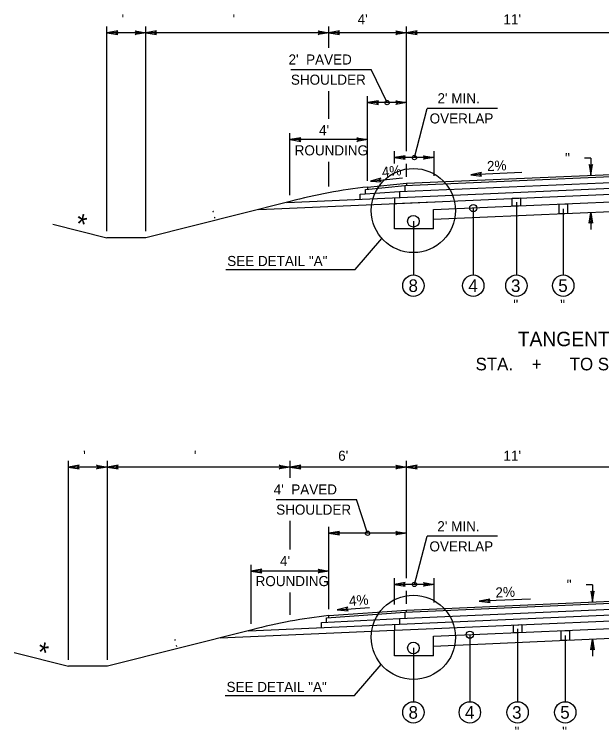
# Model space of a CAD drawing. Extents: x -592 to 1199, y -590 to 416.
# Drawn here: x -127.8 to -46.2, y 170.1 to 269.4 of the extents above; entities that cross this region are included whole.
import ezdxf

# ---------------------------------------------------------------- set-up
doc = ezdxf.new("R2010")
doc.units = 0
doc.layers.add('1', color=7, linetype='Continuous')
doc.layers.add('Des_ Drain_ Ftrs', color=7, linetype='Continuous')

msp = doc.modelspace()

# ---------------------------------------------------------------- linework, layer by layer
at = {"layer": '1'}
for p, q in [((-114.945, 239.248), (-114.945, 267.693)), ((-109.556, 239.248), (-109.556, 267.693)), ((-84.139, 264.7), (-84.139, 267.693)), ((-73.363, 250.367), (-73.363, 267.693)), ((-109.556, 266.813), (-114.945, 266.813)), ((-84.139, 266.813), (-109.556, 266.813)), ((-73.363, 266.813), (-84.139, 266.813)), ((-43.728, 266.813), (-73.363, 266.813)), ((-89.405, 261.692), (-78.264, 261.692)), ((-76.057, 257.11), (-78.264, 261.692)), ((-84.145, 254.87), (-84.145, 258.709)), ((-78.751, 246.264), (-78.751, 257.99)), ((-73.363, 257.11), (-78.751, 257.11)), ((-72.262, 249.487), (-70.472, 256.314)), ((-60.708, 256.314), (-70.472, 256.314)), ((-89.533, 244.254), (-89.533, 252.851)), ((-78.751, 251.971), (-89.528, 251.971)), ((-75.005, 248.668), (-75.005, 250.367)), ((-69.519, 246.958), (-69.519, 250.367)), ((-69.519, 249.487), (-75.005, 249.487)), ((-47.754, 249.397), (-48.634, 249.397)), ((-47.754, 249.397), (-47.754, 247.028)), ((-84.145, 245.487), (-84.145, 248.897)), ((-73.363, 246.79), (-73.363, 248.607)), ((-73.369, 245.91), (-43.728, 247.204)), ((-57.336, 247.389), (-64.422, 247.08)), ((-78.37, 246.214), (-73.893, 246.651)), ((-73.603, 245.601), (-43.728, 246.906)), ((-89.953, 243.269), (-43.728, 245.287)), ((-79.055, 245.054), (-73.603, 245.601)), ((-78.751, 245.384), (-73.369, 245.91)), ((-78.751, 245.384), (-78.751, 245.084)), ((-74.306, 244.762), (-43.728, 246.097)), ((-73.603, 245.601), (-73.603, 244.792)), ((-73.368, 245.91), (-73.368, 245.61)), ((-93.874, 242.289), (-43.728, 244.478)), ((-79.783, 244.397), (-74.306, 244.762)), ((-79.783, 243.713), (-79.783, 244.397)), ((-79.055, 244.446), (-79.055, 245.054)), ((-74.306, 244.762), (-74.306, 243.952)), ((-89.528, 243.376), (-109.556, 238.368)), ((-75.01, 243.922), (-75.01, 242.964)), ((-75.01, 243.113), (-69.524, 243.352)), ((-69.621, 242.269), (-43.728, 243.4)), ((-58.086, 243.311), (-58.086, 233.194)), ((-75.01, 239.574), (-75.01, 243.113)), ((-69.621, 239.574), (-69.621, 242.269)), ((-64.079, 242.482), (-64.079, 233.194)), ((-51.585, 242.384), (-51.585, 233.194)), ((-69.621, 240.921), (-43.728, 242.052)), ((-47.754, 241.876), (-47.754, 239.508)), ((-122.48, 240.251), (-114.945, 238.368)), ((-72.396, 240.645), (-72.396, 233.194)), ((-69.621, 239.574), (-75.01, 239.574)), ((-109.556, 238.368), (-114.945, 238.368)), ((-80.5, 233.931), (-76.76, 238.25)), ((-98.431, 233.931), (-80.5, 233.931)), ((-120.277, 179.796), (-120.277, 207.406)), ((-114.888, 206.526), (-120.277, 206.526)), ((-114.888, 179.796), (-114.888, 207.406)), ((-89.528, 206.526), (-114.888, 206.526)), ((-89.528, 205.027), (-89.528, 207.406)), ((-73.363, 206.526), (-89.528, 206.526)), ((-73.363, 191.138), (-73.363, 207.406)), ((-43.728, 206.526), (-73.363, 206.526)), ((-91.442, 202.027), (-80.301, 202.027)), ((-78.751, 197.356), (-80.301, 202.027)), ((-89.528, 195.085), (-89.528, 199.058)), ((-84.14, 186.794), (-84.14, 198.236)), ((-73.363, 197.356), (-84.14, 197.356)), ((-72.262, 190.258), (-70.5, 196.924)), ((-60.736, 196.924), (-70.5, 196.924)), ((-94.916, 184.788), (-94.916, 192.989)), ((-84.14, 192.109), (-94.916, 192.109)), ((-75.005, 187.452), (-75.005, 191.138)), ((-69.519, 187.738), (-69.519, 191.138)), ((-69.519, 190.258), (-75.005, 190.258)), ((-47.527, 190.188), (-48.407, 190.188)), ((-47.527, 190.188), (-47.527, 187.819)), ((-89.528, 186.017), (-89.528, 189.128)), ((-73.363, 187.57), (-73.363, 189.378)), ((-73.603, 186.381), (-43.728, 187.685)), ((-73.372, 186.69), (-43.728, 187.985)), ((-56.156, 188.213), (-63.242, 187.903)), ((-84.138, 185.914), (-73.372, 186.69)), ((-82.965, 186.742), (-78.478, 187.065)), ((-74.31, 185.541), (-43.728, 186.876)), ((-73.372, 186.389), (-73.372, 186.69)), ((-95.284, 183.816), (-43.728, 186.067)), ((-84.442, 185.592), (-73.603, 186.381)), ((-84.138, 185.614), (-84.138, 185.914)), ((-73.603, 186.381), (-73.603, 185.566)), ((-85.17, 184.942), (-74.31, 185.541)), ((-85.17, 184.257), (-85.17, 184.942)), ((-84.442, 184.982), (-84.442, 185.592)), ((-75.01, 184.699), (-75.01, 183.892)), ((-74.31, 185.541), (-74.31, 184.726)), ((-69.524, 184.131), (-43.728, 185.258)), ((-94.788, 183.94), (-114.888, 178.916)), ((-99.206, 182.835), (-75.01, 183.892)), ((-75.01, 183.892), (-69.524, 184.132)), ((-75.01, 180.354), (-75.01, 183.892)), ((-69.621, 183.048), (-43.728, 184.179)), ((-57.926, 184.098), (-57.926, 173.973)), ((-69.621, 180.354), (-69.621, 183.048)), ((-69.621, 181.7), (-43.728, 182.831)), ((-64.556, 183.27), (-64.556, 173.973)), ((-51.312, 183.175), (-51.312, 173.973)), ((-47.527, 182.667), (-47.527, 180.299)), ((-127.812, 180.799), (-120.277, 178.916)), ((-72.396, 181.425), (-72.396, 173.973)), ((-69.621, 180.354), (-75.01, 180.354)), ((-114.888, 178.916), (-120.277, 178.916)), ((-80.595, 174.82), (-76.855, 179.14)), ((-98.527, 174.82), (-80.595, 174.82))]:
    msp.add_line(p, q, dxfattribs=at)
for points in [[(-58.66, 243.827), (-57.513, 243.877), (-57.513, 242.798), (-58.66, 242.748)], [(-52.158, 243.032), (-51.012, 243.082), (-51.012, 241.734), (-52.158, 241.684)], [(-58.499, 184.613), (-57.353, 184.663), (-57.353, 183.584), (-58.499, 183.534)], [(-51.885, 183.823), (-50.739, 183.873), (-50.739, 182.525), (-51.885, 182.475)]]:
    msp.add_lwpolyline(points, close=True, dxfattribs=at)
for centre, radius in [((-76.057, 257.11), 0.3), ((-72.262, 249.487), 0.3), ((-72.398, 242.133), 5.838), ((-64.079, 242.482), 0.5), ((-72.396, 240.645), 0.808), ((-72.396, 231.708), 1.485), ((-64.079, 231.708), 1.485), ((-58.086, 231.708), 1.485), ((-51.585, 231.708), 1.485), ((-78.751, 197.356), 0.3), ((-72.262, 190.258), 0.3), ((-72.398, 182.912), 5.838), ((-64.556, 183.269), 0.5), ((-72.396, 181.425), 0.808), ((-72.396, 172.488), 1.485), ((-64.556, 172.488), 1.485), ((-57.926, 172.488), 1.485), ((-51.312, 172.488), 1.485)]:
    msp.add_circle(centre, radius, dxfattribs=at)
for centre, end in [((-71.869, 178.55), 105.23809), ((-77.256, 119.08), 105.12625)]:
    msp.add_arc(centre, 67.188, 95.87953, end, dxfattribs=at)
at = {"layer": 'Des_ Drain_ Ftrs'}
for points in [[(-114.945, 266.813), (-113.456, 266.565), (-113.751, 266.813), (-113.456, 267.062)], [(-109.556, 266.813), (-111.045, 266.565), (-110.75, 266.813), (-111.045, 267.062)], [(-109.556, 266.813), (-108.068, 266.565), (-108.363, 266.813), (-108.068, 267.062)], [(-84.139, 266.813), (-85.628, 266.565), (-85.333, 266.813), (-85.628, 267.062)], [(-84.139, 266.813), (-82.651, 266.565), (-82.946, 266.813), (-82.651, 267.062)], [(-73.363, 266.813), (-74.851, 266.565), (-74.556, 266.813), (-74.851, 267.062)], [(-73.363, 266.813), (-71.875, 266.565), (-72.17, 266.813), (-71.875, 267.062)], [(-78.751, 257.11), (-77.263, 256.861), (-77.558, 257.11), (-77.263, 257.358)], [(-73.363, 257.11), (-74.851, 256.861), (-74.556, 257.11), (-74.851, 257.358)], [(-89.528, 251.971), (-88.039, 251.723), (-88.334, 251.971), (-88.039, 252.22)], [(-78.751, 251.971), (-80.24, 251.723), (-79.945, 251.971), (-80.24, 252.22)], [(-75.005, 249.487), (-73.517, 249.239), (-73.812, 249.487), (-73.517, 249.735)], [(-69.519, 249.487), (-71.007, 249.239), (-70.712, 249.487), (-71.007, 249.735)], [(-47.754, 247.028), (-47.506, 248.517), (-47.754, 248.222), (-48.002, 248.517)], [(-64.422, 247.08), (-62.924, 246.897), (-63.23, 247.132), (-62.946, 247.393)], [(-78.37, 246.214), (-76.864, 246.11), (-77.182, 246.329), (-76.912, 246.604)], [(-47.754, 241.876), (-47.506, 240.388), (-47.754, 240.683), (-48.002, 240.388)], [(-120.277, 206.526), (-118.789, 206.278), (-119.084, 206.526), (-118.789, 206.774)], [(-114.888, 206.526), (-116.377, 206.278), (-116.082, 206.526), (-116.377, 206.774)], [(-114.888, 206.526), (-113.4, 206.278), (-113.695, 206.526), (-113.4, 206.774)], [(-89.528, 206.526), (-91.016, 206.278), (-90.721, 206.526), (-91.016, 206.774)], [(-89.528, 206.526), (-88.04, 206.278), (-88.335, 206.526), (-88.04, 206.774)], [(-73.363, 206.526), (-74.851, 206.278), (-74.556, 206.526), (-74.851, 206.774)], [(-73.363, 206.526), (-71.875, 206.278), (-72.17, 206.526), (-71.875, 206.774)], [(-84.14, 197.356), (-82.651, 197.107), (-82.946, 197.356), (-82.651, 197.604)], [(-73.363, 197.356), (-74.851, 197.107), (-74.556, 197.356), (-74.851, 197.604)], [(-94.916, 192.109), (-93.428, 191.861), (-93.723, 192.109), (-93.428, 192.357)], [(-84.14, 192.109), (-85.628, 191.861), (-85.333, 192.109), (-85.628, 192.357)], [(-75.005, 190.258), (-73.517, 190.01), (-73.812, 190.258), (-73.517, 190.506)], [(-69.519, 190.258), (-71.007, 190.01), (-70.712, 190.258), (-71.007, 190.506)], [(-47.527, 187.819), (-47.278, 189.308), (-47.527, 189.013), (-47.775, 189.308)], [(-63.242, 187.903), (-61.744, 187.72), (-62.05, 187.956), (-61.766, 188.216)], [(-82.965, 186.742), (-81.463, 186.6), (-81.774, 186.827), (-81.498, 187.095)], [(-47.527, 182.667), (-47.278, 181.179), (-47.527, 181.474), (-47.775, 181.179)]]:
    msp.add_lwpolyline(points, close=True, dxfattribs=at)

# ---------------------------------------------------------------- texts
at = {"layer": '1'}
for s, height, p in [(" '", 1.4, (-113.445, 267.964)), ("  '", 1.4, (-98.544, 267.964)), ("4'", 1.4, (-80.141, 267.964)), ("11'", 1.4, (-59.893, 267.964)), ("2'  PAVED", 1.4, (-89.732, 262.392)), ('SHOULDER', 1.4, (-89.406, 259.592)), ("2' MIN.", 1.4, (-69.048, 257.014)), ('OVERLAP', 1.4, (-70.137, 254.214)), ("4'", 1.4, (-85.492, 252.587)), ('ROUNDING', 1.4, (-88.881, 249.787)), ('SEE DETAIL "A"', 1.4, (-98.246, 234.434)), ('8', 1.75, (-73.069, 230.833)), ('4', 1.75, (-64.755, 230.833)), ('3', 1.75, (-58.842, 230.833)), ('5', 1.75, (-52.276, 230.833)), (' "', 1.4, (-59.03, 228.349)), (' "', 1.4, (-52.528, 228.349)), ('TANGENT SECTIONS', 2, (-57.903, 223.31)), ('STA.    +      TO STA.    +     ', 1.75, (-63.757, 219.954)), (" '", 1.4, (-118.778, 207.407)), ("  '", 1.4, (-103.904, 207.407)), ("6'", 1.4, (-82.836, 207.407)), ("11'", 1.4, (-59.893, 207.407)), ("4'  PAVED", 1.4, (-91.792, 202.727)), ('SHOULDER', 1.4, (-91.443, 199.927)), ("2' MIN.", 1.4, (-69.075, 197.624)), ('OVERLAP', 1.4, (-70.165, 194.824)), ("4'", 1.4, (-90.918, 192.809)), ('ROUNDING', 1.4, (-94.307, 190.009)), ('SEE DETAIL "A"', 1.4, (-98.341, 175.324)), ('8', 1.75, (-73.069, 171.613)), ('4', 1.75, (-65.231, 171.613)), ('3', 1.75, (-58.682, 171.613)), ('5', 1.75, (-52.003, 171.613)), (' "', 1.4, (-58.87, 169.128)), (' "', 1.4, (-52.256, 169.128))]:
    msp.add_text(s, height=height, dxfattribs=at).set_placement(p)
for s, height, rotation, p in [('  "', 1.4, 0.14377, (-52.366, 248.693)), ('4%', 1.4, 5.85995, (-76.702, 246.762)), ('2%', 1.4, 2.62348, (-62.145, 247.594)), ('*', 2.8, 347.15207, (-119.538, 239.064)), (' : ', 1.4, 14.22821, (-100.722, 240.859)), ('  "', 1.4, 0.14377, (-52.139, 189.484)), ('2%', 1.4, 2.62623, (-60.965, 188.418)), ('4%', 1.4, 4.4031, (-81.284, 187.247)), (' : ', 1.4, 14.22821, (-106.018, 181.415)), ('*', 2.8, 347.15207, (-124.87, 179.612))]:
    msp.add_text(s, height=height, rotation=rotation, dxfattribs=at).set_placement(p)

doc.saveas('drawing.dxf')
